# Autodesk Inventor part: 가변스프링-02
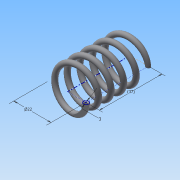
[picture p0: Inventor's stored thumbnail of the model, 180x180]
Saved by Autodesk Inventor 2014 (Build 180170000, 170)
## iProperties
Created: 2015-09
Part Number: 가변스프링-02
Material: 강철, 탄소
Document SubType Name: Modeling
Designer: study
Density: 7.87 g/cm^3
Appearance: 반연마
Mass: 18.7976 g
Surface Area: 32.4648 cm^2
Volume: 2.38851 cm^3
Author: study
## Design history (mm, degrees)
sketch "스케치1"
  geometry: L1 (0, 0)-(11, 0); L2 (11, 0)-(11, 29.043); L3 (11, 29.043)-(0, 29.043); L4 (0, 29.043)-(0, 0); C1 r 1.5 at (11, 0)
  constraints: 8 end point, 2 parallel, 1 centre point, 1 coincident, 1 horizontal, 1 perpendicular
  dimensions: "d0" = 22 diameter of L2 L4; "d1" = 3 diameter of C1; "d2" = 29.04259 distance of L1.end L2.end (derived)
feature "코일1" sketch "스케치1" pitch "d3" = 10; turns "d5" = 5; dims "d4" = 29.04259 (= d2), "d6" = 0, angle "d7" = 90 deg, angle "d8" = 90 deg, "d9" = 0, "d10" = 0
sketch "스케치2"
  geometry: L1 (-12.5, 0)-(-9.5, 0) reference; 1 further point
  constraints: 1 horizontal alignment
extrude "돌출1" cut sketch "스케치2" stored distance "d11" = 10; taper "d12" = 0 deg
node "작업 평면1"
sketch "스케치3"
  geometry: L1 (-9.5, 0)-(-12.5, 0) reference; 1 further point
  constraints: 1 horizontal alignment
extrude "돌출2" cut sketch "스케치3" stored distance "d14" = 10; taper "d15" = 0 deg
node "솔리드1"
node "절단 모서리 투영1"
node "절단 모서리 투영2"
other parameters: "d13" = 29.04259 (= d2)
